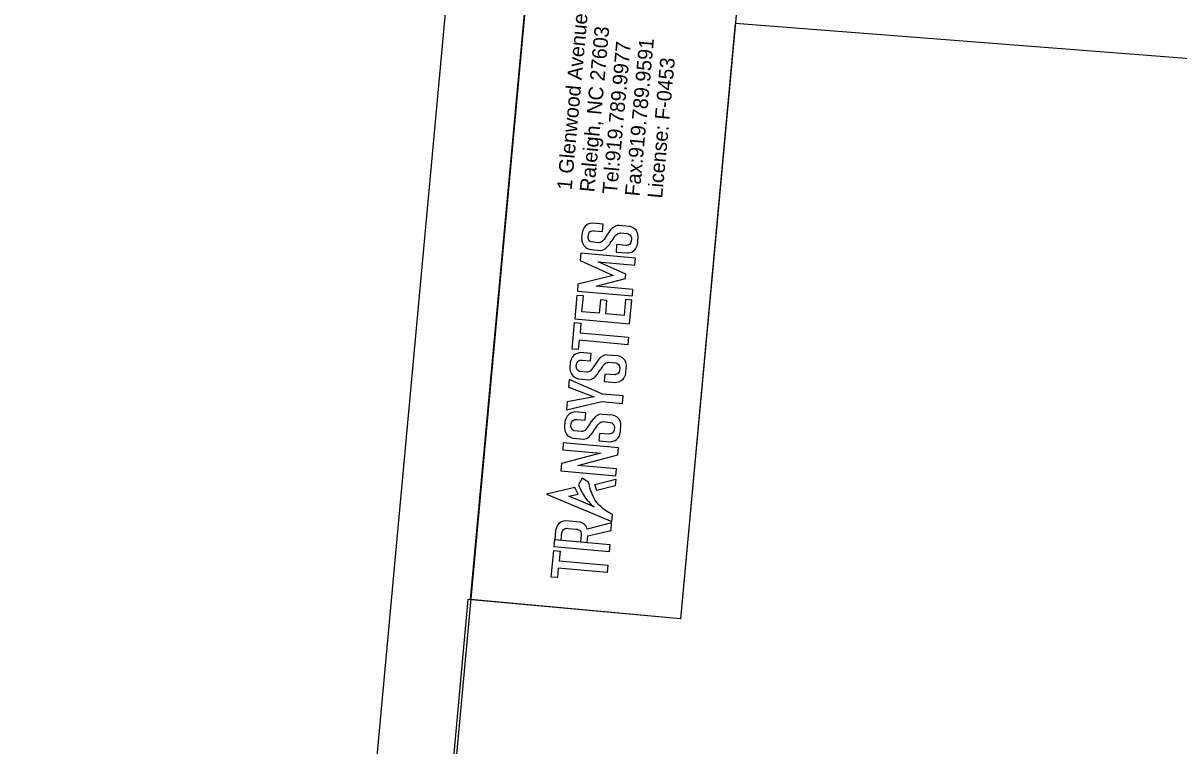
# Model space of a CAD drawing. Extents: x 2011671 to 2012922, y 444832 to 446720.
# Drawn here: x 2011670.5 to 2012036.3, y 446248.3 to 446477.1 of the extents above; entities that cross this region are included whole.
import ezdxf

# ---------------------------------------------------------------- set-up
doc = ezdxf.new("R2010")
doc.units = 0
for name, color, linetype in [('Old_Level_1', 7, 'Continuous'), ('Old_Level_2', 7, 'Continuous'), ('Old_Level_58', 7, 'Continuous'), ('Sheet Clip Boundary CELL', 7, 'Continuous'), ('Sheet Plan And Profile CELL', 7, 'Continuous'), ('Sheet Plot Border Outside CELL', 7, 'Continuous')]:
    doc.layers.add(name, color=color, linetype=linetype)

msp = doc.modelspace()

# ---------------------------------------------------------------- linework, layer by layer
at = {"layer": 'Old_Level_1'}
for points in [[(2011853.85, 446411.13), (2011854.06, 446413.43), (2011850.6, 446413.75), (2011849.88, 446413.62), (2011849.26, 446413.39), (2011848.85, 446413.13), (2011848.46, 446412.79), (2011848.14, 446412.38), (2011847.93, 446411.97), (2011847.93, 446411.97), (2011847.69, 446411.53), (2011847.53, 446411.06), (2011847.42, 446410.75), (2011847.3, 446409.01), (2011847.34, 446408.47), (2011847.37, 446408.01), (2011847.57, 446407.53), (2011847.74, 446407.11), (2011847.99, 446406.69), (2011848.27, 446406.35), (2011848.62, 446406.08), (2011848.99, 446405.85), (2011849.66, 446405.53), (2011850.17, 446405.43), (2011853.33, 446405.14), (2011853.81, 446405.21), (2011854.32, 446405.4), (2011854.76, 446405.64), (2011855.09, 446405.91), (2011855.48, 446406.33), (2011855.87, 446406.75), (2011856.11, 446407.01), (2011856.38, 446407.47), (2011856.65, 446407.93), (2011856.94, 446408.3), (2011857.26, 446408.71), (2011857.58, 446409.21), (2011857.84, 446409.62), (2011858.19, 446410.02), (2011858.51, 446410.3), (2011858.77, 446410.53), (2011859.26, 446410.64), (2011859.57, 446410.71), (2011861.79, 446410.47), (2011862.26, 446410.26), (2011862.66, 446409.98), (2011862.92, 446409.63), (2011863.05, 446409.26), (2011863.08, 446408.91), (2011863.02, 446407.95), (2011862.9, 446407.64), (2011862.68, 446407.33), (2011862.45, 446407.02), (2011862.11, 446406.91), (2011861.76, 446406.8), (2011861.48, 446406.71), (2011858.38, 446406.96), (2011858.19, 446404.63), (2011861.89, 446404.33), (2011862.18, 446404.42), (2011863.07, 446404.61), (2011863.37, 446404.76), (2011863.71, 446404.98), (2011864.12, 446405.33), (2011864.34, 446405.61), (2011864.56, 446406.03), (2011864.64, 446406.18), (2011864.86, 446406.59), (2011864.97, 446407.12), (2011865.04, 446407.51), (2011865.18, 446409.65), (2011865.1, 446410.25), (2011864.8, 446411.11), (2011864.7, 446411.4), (2011863.97, 446412.09), (2011863.22, 446412.49), (2011862.52, 446412.71), (2011859.11, 446412.97), (2011858.64, 446413.01), (2011858.25, 446412.91), (2011857.88, 446412.75), (2011857.08, 446412.29), (2011856.46, 446411.63), (2011855.79, 446410.71), (2011855.28, 446410.01), (2011854.38, 446408.63), (2011853.76, 446407.93), (2011853.31, 446407.64), (2011853.02, 446407.59), (2011852.73, 446407.54), (2011850.31, 446407.8), (2011850.07, 446407.95), (2011849.83, 446408.1), (2011849.69, 446408.29), (2011849.52, 446408.54), (2011849.43, 446408.81), (2011849.35, 446409.07), (2011849.39, 446409.22), (2011849.32, 446409.24), (2011849.42, 446410.19), (2011849.56, 446410.46), (2011849.69, 446410.72), (2011849.83, 446410.99), (2011850.03, 446411.1), (2011850.33, 446411.26), (2011850.61, 446411.33), (2011850.89, 446411.39), (2011851.19, 446411.36)], [(2011857.28, 446397.23), (2011846.06, 446394.43), (2011845.96, 446392.22), (2011863.36, 446390.71), (2011863.54, 446392.81), (2011851.9, 446393.82), (2011861.15, 446396.25), (2011861.31, 446397.59), (2011852.5, 446401.48), (2011864.17, 446400.46), (2011864.37, 446402.73), (2011847.02, 446404.25), (2011846.82, 446401.97)], [(2011845.8, 446390.88), (2011845.13, 446383.52), (2011862.49, 446381.94), (2011863.17, 446389.39), (2011861.2, 446389.56), (2011860.75, 446384.54), (2011854.93, 446385.07), (2011855.31, 446389.27), (2011853.24, 446389.46), (2011852.86, 446385.22), (2011847.38, 446385.72), (2011847.84, 446390.71)], [(2011844.25, 446373.88), (2011845.01, 446382.31), (2011847.08, 446382.12), (2011846.8, 446379.02), (2011862.16, 446377.63), (2011861.94, 446375.29), (2011846.48, 446376.69), (2011846.21, 446373.73)], [(2011850.12, 446370.17), (2011850.33, 446372.47), (2011846.87, 446372.78), (2011846.15, 446372.65), (2011845.54, 446372.43), (2011845.12, 446372.17), (2011844.74, 446371.83), (2011844.41, 446371.42), (2011844.2, 446371.01), (2011844.2, 446371.01), (2011843.97, 446370.57), (2011843.8, 446370.1), (2011843.69, 446369.79), (2011843.57, 446368.04), (2011843.61, 446367.51), (2011843.65, 446367.05), (2011843.84, 446366.57), (2011844.02, 446366.14), (2011844.26, 446365.72), (2011844.55, 446365.39), (2011844.89, 446365.11), (2011845.26, 446364.88), (2011845.93, 446364.57), (2011846.44, 446364.47), (2011849.6, 446364.18), (2011850.08, 446364.25), (2011850.6, 446364.43), (2011851.03, 446364.68), (2011851.37, 446364.95), (2011851.75, 446365.37), (2011852.14, 446365.79), (2011852.39, 446366.05), (2011852.66, 446366.51), (2011852.92, 446366.97), (2011853.21, 446367.33), (2011853.54, 446367.75), (2011853.85, 446368.25), (2011854.11, 446368.66), (2011854.46, 446369.06), (2011854.78, 446369.34), (2011855.04, 446369.57), (2011855.54, 446369.68), (2011855.84, 446369.74), (2011858.07, 446369.5), (2011858.53, 446369.3), (2011858.93, 446369.02), (2011859.19, 446368.66), (2011859.32, 446368.29), (2011859.36, 446367.95), (2011859.29, 446366.99), (2011859.17, 446366.68), (2011858.95, 446366.37), (2011858.72, 446366.06), (2011858.38, 446365.95), (2011858.03, 446365.83), (2011857.76, 446365.75), (2011854.65, 446366), (2011854.47, 446363.66), (2011858.16, 446363.37), (2011858.46, 446363.46), (2011859.34, 446363.65), (2011859.65, 446363.8), (2011859.99, 446364.02), (2011860.39, 446364.36), (2011860.61, 446364.65), (2011860.84, 446365.07), (2011860.92, 446365.22), (2011861.14, 446365.63), (2011861.24, 446366.16), (2011861.31, 446366.54), (2011861.46, 446368.68), (2011861.37, 446369.29), (2011861.07, 446370.14), (2011860.97, 446370.43), (2011860.24, 446371.12), (2011859.49, 446371.53), (2011858.8, 446371.75), (2011855.38, 446372.01), (2011854.91, 446372.05), (2011854.53, 446371.95), (2011854.16, 446371.79), (2011853.35, 446371.32), (2011852.73, 446370.67), (2011852.06, 446369.75), (2011851.55, 446369.05), (2011850.66, 446367.66), (2011850.03, 446366.96), (2011849.58, 446366.68), (2011849.29, 446366.62), (2011849, 446366.57), (2011846.58, 446366.84), (2011846.34, 446366.99), (2011846.1, 446367.13), (2011845.96, 446367.33), (2011845.79, 446367.57), (2011845.71, 446367.84), (2011845.62, 446368.11), (2011845.67, 446368.25), (2011845.59, 446368.28), (2011845.7, 446369.23), (2011845.83, 446369.49), (2011845.96, 446369.76), (2011846.1, 446370.03), (2011846.3, 446370.14), (2011846.6, 446370.3), (2011846.88, 446370.36), (2011847.16, 446370.43), (2011847.47, 446370.39)], [(2011842.74, 446357.19), (2011842.51, 446354.66), (2011853.68, 446357.27), (2011860.19, 446356.7), (2011860.4, 446359.08), (2011853.93, 446359.64), (2011843.35, 446364.29), (2011843.19, 446361.8), (2011851.29, 446358.74)], [(2011848.41, 446351.37), (2011848.62, 446353.67), (2011845.16, 446353.99), (2011844.44, 446353.86), (2011843.82, 446353.63), (2011843.41, 446353.37), (2011843.02, 446353.03), (2011842.7, 446352.62), (2011842.49, 446352.22), (2011842.49, 446352.22), (2011842.26, 446351.78), (2011842.09, 446351.31), (2011841.98, 446351), (2011841.86, 446349.25), (2011841.9, 446348.71), (2011841.94, 446348.25), (2011842.13, 446347.77), (2011842.31, 446347.35), (2011842.55, 446346.93), (2011842.84, 446346.59), (2011843.18, 446346.32), (2011843.55, 446346.09), (2011844.22, 446345.77), (2011844.73, 446345.67), (2011847.89, 446345.38), (2011848.37, 446345.46), (2011848.88, 446345.64), (2011849.32, 446345.89), (2011849.66, 446346.15), (2011850.04, 446346.57), (2011850.43, 446346.99), (2011850.68, 446347.25), (2011850.94, 446347.71), (2011851.21, 446348.17), (2011851.5, 446348.54), (2011851.83, 446348.95), (2011852.14, 446349.45), (2011852.4, 446349.87), (2011852.75, 446350.26), (2011853.07, 446350.55), (2011853.33, 446350.77), (2011853.83, 446350.88), (2011854.13, 446350.95), (2011856.36, 446350.71), (2011856.82, 446350.5), (2011857.22, 446350.22), (2011857.48, 446349.87), (2011857.61, 446349.5), (2011857.65, 446349.15), (2011857.58, 446348.19), (2011857.46, 446347.88), (2011857.24, 446347.57), (2011857.01, 446347.26), (2011856.67, 446347.15), (2011856.32, 446347.04), (2011856.05, 446346.95), (2011852.94, 446347.2), (2011852.76, 446344.87), (2011856.45, 446344.57), (2011856.75, 446344.67), (2011857.63, 446344.86), (2011857.94, 446345), (2011858.28, 446345.23), (2011858.68, 446345.57), (2011858.9, 446345.85), (2011859.13, 446346.27), (2011859.21, 446346.42), (2011859.43, 446346.83), (2011859.53, 446347.36), (2011859.6, 446347.75), (2011859.74, 446349.89), (2011859.66, 446350.49), (2011859.36, 446351.35), (2011859.26, 446351.64), (2011858.53, 446352.33), (2011857.78, 446352.74), (2011857.09, 446352.95), (2011853.67, 446353.21), (2011853.2, 446353.25), (2011852.82, 446353.15), (2011852.45, 446353), (2011851.64, 446352.53), (2011851.02, 446351.87), (2011850.35, 446350.96), (2011849.84, 446350.26), (2011848.95, 446348.87), (2011848.32, 446348.17), (2011847.87, 446347.88), (2011847.58, 446347.83), (2011847.29, 446347.78), (2011844.87, 446348.05), (2011844.63, 446348.19), (2011844.39, 446348.34), (2011844.25, 446348.53), (2011844.08, 446348.78), (2011844, 446349.05), (2011843.91, 446349.32), (2011843.95, 446349.46), (2011843.88, 446349.48), (2011843.99, 446350.43), (2011844.12, 446350.7), (2011844.25, 446350.97), (2011844.39, 446351.23), (2011844.59, 446351.34), (2011844.89, 446351.5), (2011845.17, 446351.57), (2011845.45, 446351.64), (2011845.76, 446351.6)], [(2011840.74, 446335.31), (2011858.12, 446333.73), (2011858.33, 446335.95), (2011846.1, 446337.07), (2011858.76, 446340.37), (2011858.94, 446342.62), (2011841.5, 446344.2), (2011841.31, 446342.03), (2011853.24, 446340.95), (2011840.95, 446337.66)], [(2011836.23, 446327.92), (2011856.86, 446319.33), (2011857.05, 446321.55), (2011856.25, 446321.96), (2011855.15, 446322.64), (2011854.55, 446323.01), (2011854.05, 446323.43), (2011853.34, 446324.02), (2011852.9, 446324.39), (2011852.55, 446324.81), (2011852.19, 446325.22), (2011851.74, 446325.75), (2011851.51, 446326.18), (2011851.22, 446326.63), (2011850.95, 446327.21), (2011850.71, 446327.73), (2011850.26, 446328.99), (2011849.94, 446330.02), (2011849.53, 446331.71), (2011847.5, 446333.04), (2011846.35, 446330.96), (2011847.08, 446329.26), (2011847.86, 446327.8), (2011848.56, 446326.75), (2011848.94, 446326.19), (2011849.46, 446325.61), (2011849.97, 446325.02), (2011850.36, 446324.59), (2011850.97, 446324.15), (2011851.31, 446323.91), (2011843.21, 446327.29), (2011846.18, 446328.02), (2011845.1, 446330.03)], [(2011852.1, 446329.09), (2011851.52, 446331.07), (2011858.13, 446332.73), (2011857.87, 446330.65)], [(2011840.85, 446313.41), (2011841.07, 446315.79), (2011841.15, 446316.09), (2011841.35, 446316.47), (2011841.59, 446316.78), (2011841.89, 446316.98), (2011842.23, 446317.11), (2011842.49, 446317.2), (2011843.07, 446317.15), (2011845.55, 446316.93), (2011845.88, 446316.84), (2011846.31, 446316.72), (2011846.59, 446316.56), (2011846.83, 446316.34), (2011847.02, 446316.05), (2011847.13, 446315.61), (2011847.15, 446315.28), (2011847.16, 446314.95), (2011846.98, 446312.86), (2011849.08, 446312.67), (2011849.26, 446314.77), (2011856.61, 446316.48), (2011856.8, 446318.88), (2011849.05, 446316.94), (2011848.95, 446317.33), (2011848.6, 446317.9), (2011848.12, 446318.43), (2011847.52, 446318.84), (2011846.91, 446319.11), (2011846.72, 446319.11), (2011842.18, 446319.57), (2011841.42, 446319.43), (2011840.71, 446319.14), (2011840.2, 446318.77), (2011839.67, 446318.12), (2011839.38, 446317.46), (2011839.09, 446316.81), (2011839.06, 446316.41), (2011838.78, 446313.6)], [(2011838.57, 446311.3), (2011838.78, 446313.6), (2011856.27, 446312.01), (2011856.06, 446309.7)], [(2011837.68, 446301.72), (2011838.45, 446310.15), (2011840.51, 446309.96), (2011840.23, 446306.86), (2011855.59, 446305.47), (2011855.38, 446303.13), (2011839.92, 446304.53), (2011839.65, 446301.57)]]:
    msp.add_lwpolyline(points, close=True, dxfattribs=at)
at = {"layer": 'Old_Level_58'}
msp.add_lwpolyline([(2011812.16, 446294.64), (2011830.48, 446493.85), (2011896.89, 446487.74), (2011878.57, 446288.53)], close=True, dxfattribs=at)
at = {"layer": 'Sheet Clip Boundary CELL'}
msp.add_lwpolyline([(2011937.41, 445282.88), (2012176.97, 445268.45), (2012460.6, 445251.63), (2012462.38, 445271.17), (2012773.97, 445309.09), (2012872.61, 446360.11), (2012827.76, 446363.69), (2012831.12, 446402.13), (2012750.66, 446410.08), (2012511.43, 446429.21), (2011895.9, 446477), (2011878.57, 446288.47), (2011811.27, 446294.66), (2011728.04, 445379.78), (2011768.91, 445373.07), (2011729.26, 445295.72)], close=True, dxfattribs=at)
at = {"layer": 'Sheet Plan And Profile CELL'}
msp.add_lwpolyline([(2011848.79, 446693.05), (2011711.46, 445199.36), (2012757.04, 445103.22), (2012894.38, 446596.92)], close=True, dxfattribs=at)
at = {"layer": 'Sheet Plot Border Outside CELL'}
msp.add_lwpolyline([(2012765.92, 444926.66), (2012921.57, 446619.52), (2011826.19, 446720.24), (2011670.54, 445027.38)], close=True, dxfattribs=at)

# ---------------------------------------------------------------- texts
at = {"layer": 'Old_Level_2'}
for s, p in [('1 Glenwood Avenue', (2011844.11, 446424.1)), ('Raleigh, NC 27603', (2011851.28, 446423.44)), ('Tel:919.789.9977 ', (2011858.45, 446422.78)), ('Fax:919.789.9591', (2011865.61, 446422.12)), ('License: F-0453', (2011872.78, 446421.47))]:
    msp.add_text(s, height=4.6576, rotation=84.7467, dxfattribs=at).set_placement(p)

doc.saveas('drawing.dxf')
